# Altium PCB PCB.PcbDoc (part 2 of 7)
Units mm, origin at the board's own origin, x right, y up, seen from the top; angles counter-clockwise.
Board outline 243.2 x 142.8 mm, 4 copper layers (Top Layer, Layer 1, Layer 2, Bottom Layer), stack 0.603 mm thick; 451 components, 380 nets, 2276 pads, 1520 vias.
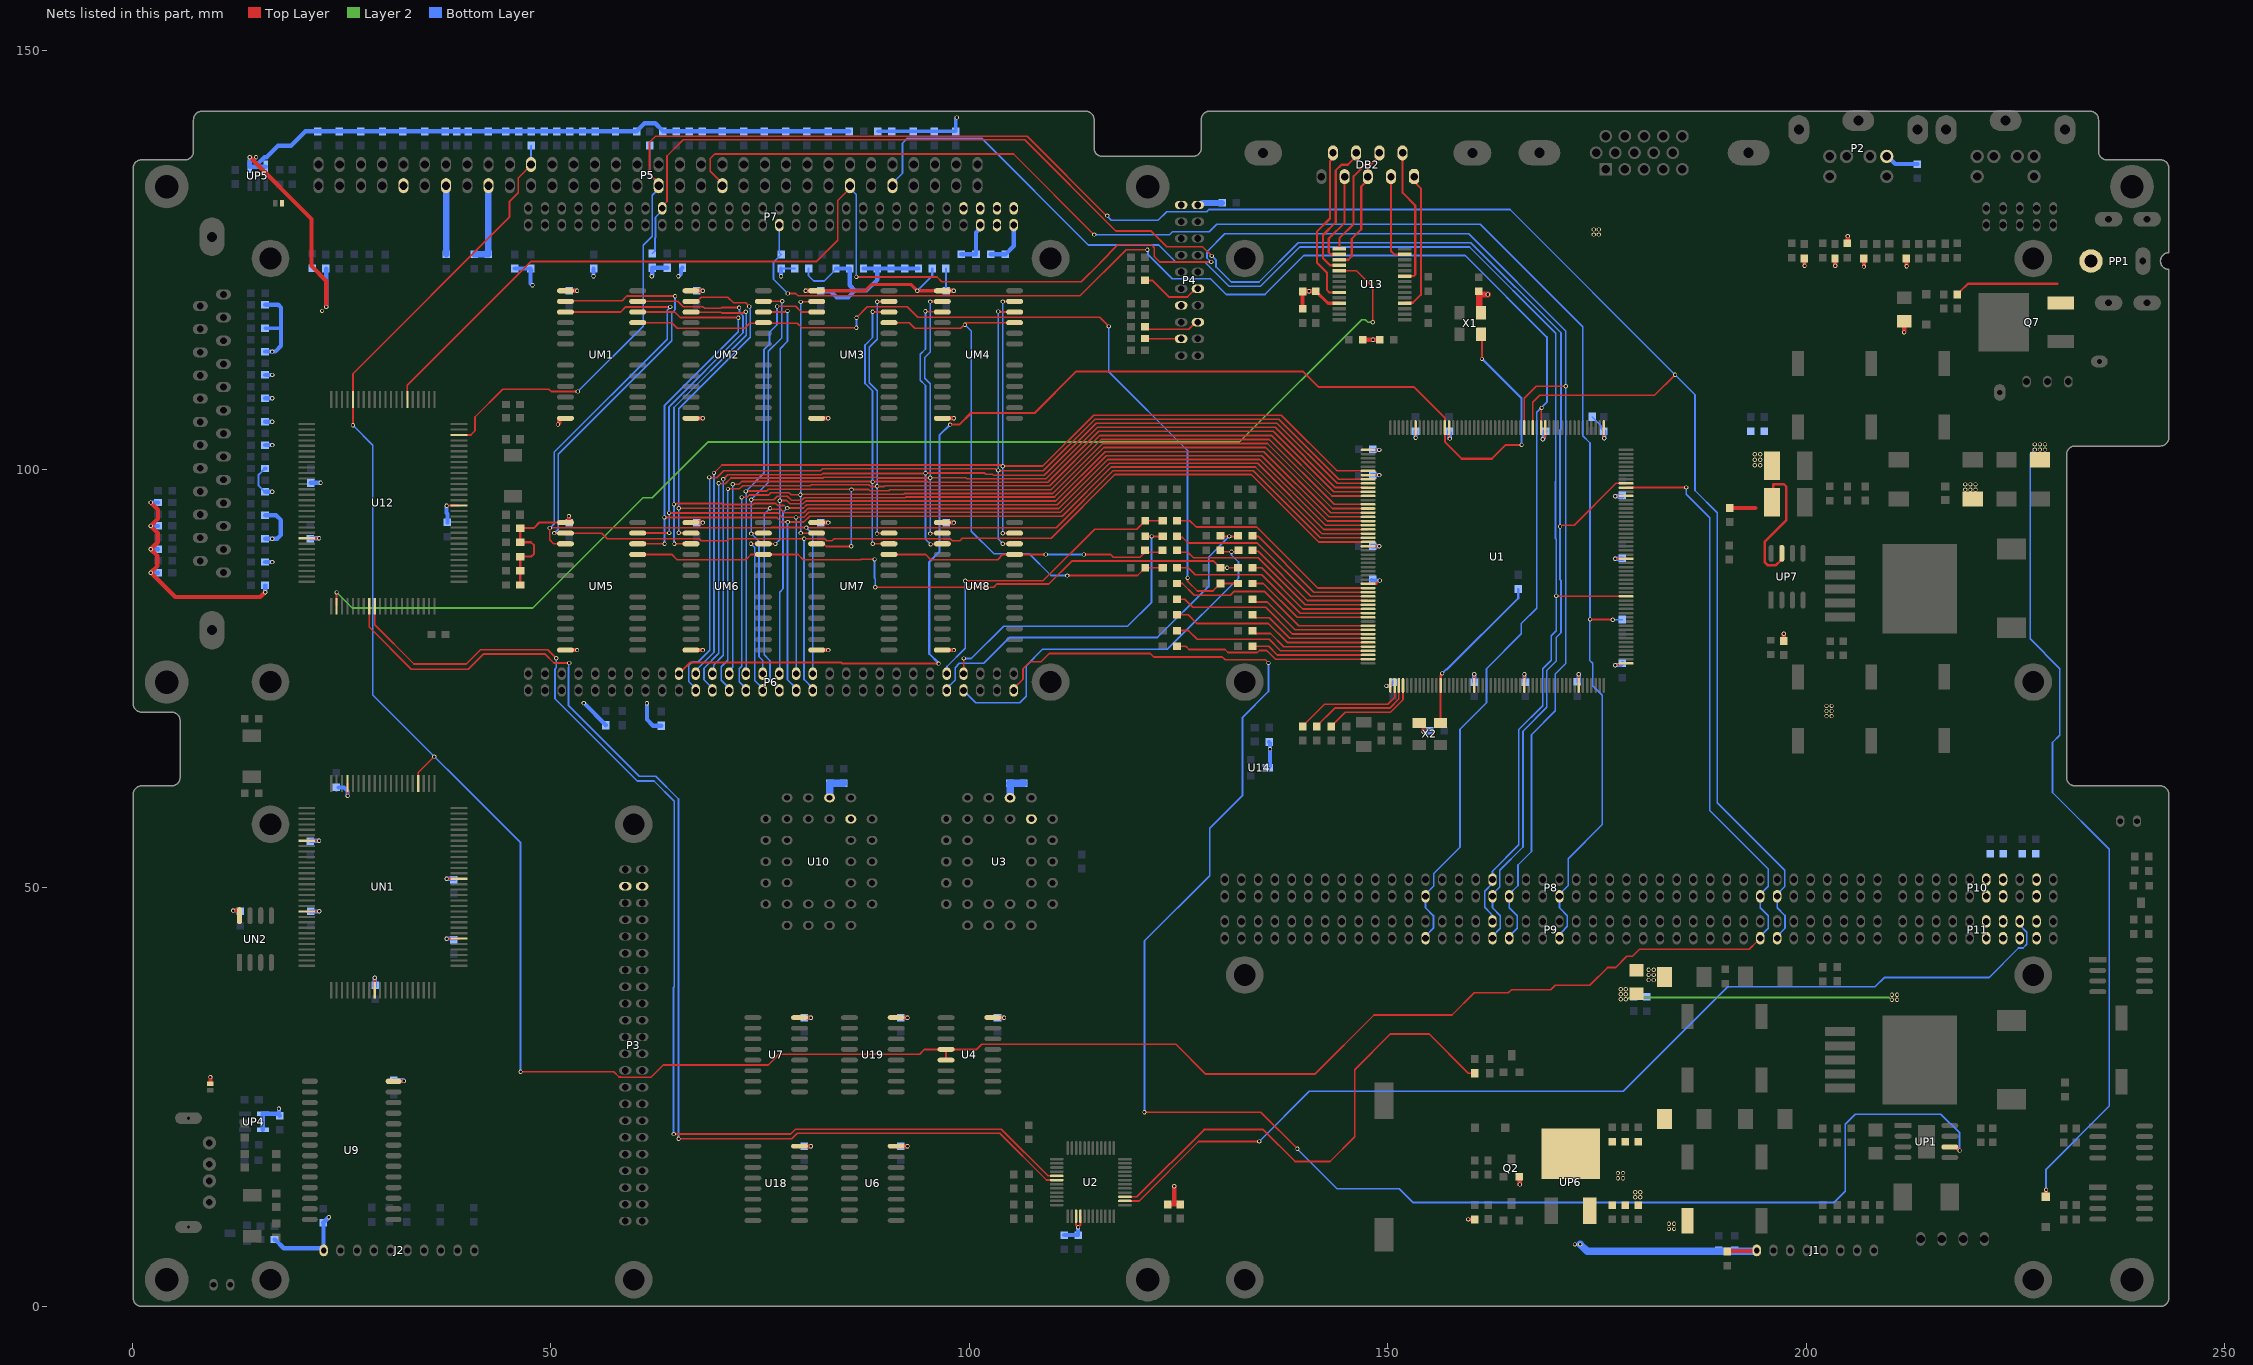
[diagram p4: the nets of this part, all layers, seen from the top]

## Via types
v1: diameter 0.508, hole 0.305, Top Layer to Bottom Layer, tented both sides, 1451 vias
v2: diameter 0.508, hole 0.3, Top Layer to Bottom Layer, 67 vias
v3: diameter 1.2, hole 1.2, Top Layer to Bottom Layer, 2 vias

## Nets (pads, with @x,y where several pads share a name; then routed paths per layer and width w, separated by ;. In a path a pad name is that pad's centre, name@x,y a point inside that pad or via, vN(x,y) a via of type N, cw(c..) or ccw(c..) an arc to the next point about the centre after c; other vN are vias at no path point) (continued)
12VSW#: R119.1 U2.27 | length 59.6
  Top Layer w0.203: U2.27@118.581,13.103 120.011,13.103 128.041,21.133 135.103,21.133 138.913,17.323 143.078,17.323 146.05,20.295 146.05,28.296 150.317,32.563 154.915,32.563 159.614,27.864 R119.1@160.376,27.864
14M: R93.1 U1.117 X2.3 | length 19.9
  Top Layer w0.254: X2.3@156.283,69.705 156.305,69.727 U1.117@156.305,74.206 156.313,74.215 156.313,75.401 156.475,75.563 v1(156.475,75.632)
  Bottom Layer w0.254: v1(156.475,75.632) 156.961,76.118 157.066,76.118 165.568,84.62 R93.1@165.568,85.717
+5V: C15.1 C16.1 C18.1 C19.1 C36.1 C37.1 C38.1 C39.1 C40.1 C41.1 C42.1 C43.1 C44.1 C45.1 C46.1 C47.1 C48.1 C49.1 C50.1 C51.1 C52.1 C53.1 C54.1 C55.1 C56.1 C57.1 C58.1 C59.1 C60.1 C61.1 C62.1 C63.1 C64.1 C65.1 C66.1 C67.1 C68.1 C69.1 C83.1 C84.1 C85.1 C119.1 C120.1 C121.1 C122.1 C123.1 C130.1 C131.1 C132.1 C133.1 C134.1 C135.1 C136.1 C137.1 C138.1 C139.1 C140.1 C141.1 C142.1 C143.1 C144.1 C145.1 C146.1 C147.1 C148.1 C149.1 J1.8 J2.10 JP1.1 JP2.1 P2.4 P3.41 P3.42 P4.19 P4.20 P7.55 P7.56 P7.57 P7.58 P10.7 P10.8 P10.9 P10.10 P11.7 P11.8 P11.9 P11.10 Q2.E R1.1 R3.2 R5.2 R21.1 R27.2 R28.2 R29.2 R30.2 R31.2 R32.2 R33.2 R34.2 R35.2 R36.2 R37.2 R38.2 R39.2 R40.2 R41.2 R42.2 R43.2 R44.2 R45.2 R46.2 R47.2 R48.2 R49.2 R50.2 R51.2 R52.2 R53.2 R54.2 R55.2 R56.2 R57.2 R58.2 R59.2 R60.2 R61.2 R62.2 R63.2 R64.2 R65.2 R66.2 R67.2 R68.2 R69.2 R70.2 R71.2 R72.2 R73.2 R74.2 R75.2 R76.2 R77.2 R78.2 R79.2 R80.2 R81.2 R82.2 R83.2 R84.2 R85.2 R86.2 R87.2 R92.1 R120.2 R121.2 R122.2 R123.2 R124.2 R125.2 R126.2 R127.2 R128.2 R129.2 R130.2 R131.2 R132.2 R133.2 R134.2 R135.2 R136.2 R137.2 R138.2 R139.2 R140.2 R141.2 R142.2 R143.2 R144.2 R152.2 RP1.1 RP2.1 RP4.2 U1.1 U1.15 U1.38 U1.46 U1.53 U1.59 U1.76 U1.85 U1.105 U1.125 U1.137 U1.150 U1.157 U1.182 U1.197 U2.15 U2.16 U3.31 U3.32 U4.16 U6.16 U7.16 U9.28 U10.31 U10.32 U12.15 U12.72 U13.11 U14.3 U18.16 U19.16 UM1.1 UM1.12 UM2.1 UM2.12 UM3.1 UM3.12 UM4.1 UM4.12 UM5.1 UM5.12 UM6.1 UM6.12 UM7.1 UM7.12 UM8.1 UM8.12 UN1.6 UN1.17 UN1.47 UN1.57 UN1.70 UN1.89 UN2.8 UP4.4 UP4.5 UP5.4 UP5.5 UP7.7 X1.4 X2.4 | length 471.1
  Top Layer w0.254: UN1.57@20.823,55.647 UN1.57@20.826,55.65 22.304,55.65 v1(22.309,55.656) ; U12.72@20.823,91.776 U12.72@20.826,91.779 22.304,91.779 v1(22.309,91.785) ; UN1.70@20.826,47.2 20.829,47.203 22.307,47.203 v1(22.312,47.209) ; UN1.47@25.698,62.478 UN1.47@25.701,62.475 25.701,60.997 v1(25.706,60.991) ; v1(28.945,39.259) 28.951,39.253 UN1.89@28.951,37.775 UN1.89@28.954,37.772 ; v1(37.542,43.944) 37.548,43.95 UN1.6@39.026,43.95 UN1.6@39.029,43.953 ; v1(37.542,51.094) 37.548,51.1 UN1.17@39.026,51.1 UN1.17@39.029,51.103 ; v1(37.542,95.673) 37.548,95.679 U12.15@39.026,95.679 U12.15@39.029,95.682 ; R143.2@46.341,86.198 R142.2@46.341,87.897 R141.2@46.341,89.597 47.657,89.597 47.992,89.932 47.992,90.926 47.614,91.303 46.348,91.303 R140.2@46.341,91.296 R139.2@46.341,92.995 47.957,92.995 48.621,93.659 UM5.1@51.739,93.659 ; U2.15@112.756,10.778 112.756,9.715 112.979,9.492 v1(112.979,9.449) 113.256,9.726 U2.16@113.256,10.778
  Top Layer w0.279: U1.85@147.647,86.336 147.651,86.34 148.598,86.34 148.989,86.731 v1(149.033,86.731) ; U1.76@147.647,90.836 147.649,90.834 v1(148.965,90.834) v1@148.967,90.831 ; U1.59@147.647,99.336 147.649,99.334 v1(148.965,99.334) v1@148.967,99.331 ; U1.53@147.647,102.336 147.649,102.334 v1(148.965,102.334) v1@148.967,102.331 ; v1(149.82,74.133) 150.295,74.133 150.305,74.142 U1.105@150.305,74.206 ; v1(153.302,103.801) 153.303,103.802 153.303,104.993 U1.46@153.305,104.994 ; U1.38@157.305,104.994 157.309,104.99 157.309,103.828 157.389,103.748 v1(157.389,103.686) ; U1.125@160.305,74.206 160.307,74.208 v1(160.307,75.524) v1@160.309,75.527 ; U1.137@166.305,74.206 166.307,74.208 v1(166.307,75.524) v1@166.309,75.527 ; v1(168.489,103.622) 168.489,103.684 168.801,103.995 168.801,104.99 U1.15@168.805,104.994 ; U1.150@172.805,74.206 172.807,74.208 v1(172.807,75.524) v1@172.809,75.527 ; U1.1@175.805,104.994 175.809,104.99 175.809,103.851 175.863,103.797 v1(175.863,103.735) ; v1@177.142,89.34 v1(177.144,89.338) 178.46,89.338 U1.182@178.463,89.336 ; v1(177.151,76.597) 177.195,76.64 177.512,76.64 177.707,76.836 U1.157@178.463,76.836 ; v1(177.177,96.796) 177.213,96.832 178.459,96.832 U1.197@178.463,96.836
  Top Layer w0.305: RP2.1@195.9,96.1 196.024,96.224 196.024,98.237 197.293,98.237 197.598,97.933 197.598,93.945 195.032,91.379 195.032,88.89 195.388,88.535 196.328,88.535 197.064,89.271 UP7.7@197.064,89.982
  Top Layer w0.381: UM3.1@81.756,121.35 87.538,121.35 88.302,122.113 93.001,122.113 v1(93.763,121.351) ; UM4.1@96.764,121.35 96.763,121.351 v1(93.763,121.351) ; C120.1@139.8,119.2 C120.1@139.808,119.208 ; C43.1@141.4,121.3 142.85,119.85 U13.11@144.2,119.85 ; v1(93.763,121.351) v1(93.763,121.351)
  Top Layer w0.508: v1(2.196,96.053) 3.059,95.189 3.059,94.123 v1(2.196,93.259) 3.034,92.421 3.034,91.303 v1(2.196,90.465) 2.983,89.678 2.983,88.458 v1(2.196,87.671) 5.117,84.75 15.277,84.75 v1(15.861,85.334) ; JP1.1@9.322,26.619 v2(9.322,27.407) ; v1(12.029,47.302) 12.743,47.302 12.79,47.255 UN2.8@12.79,46.688 ; v1(14.032,137.303) 21.398,129.937 21.398,124.298 23.151,122.545 v1(23.151,119.421) ; U9.28@31.2,26.9 31.224,26.924 32.42,26.924 v1(32.436,26.94) ; v1(50.837,105.375) 51.009,105.547 51.009,106.063 51.057,106.111 UM1.12@51.741,106.111 ; UM1.1@51.739,121.35 51.741,121.351 v1(53.123,121.351) ; UM5.1@51.74,93.66 52.111,93.66 52.157,93.706 v1(52.157,94.427) ; UM5.12@51.741,78.421 v1(53.123,78.421) ; UM6.1@66.747,93.658 UM6.1@66.747,93.659 UM6.1@66.747,93.659 v1(68.13,93.66) ; UM2.1@66.747,121.35 UM2.1@66.747,121.35 66.748,121.351 v1(68.13,121.351) ; UM6.12@66.749,78.421 v1(68.131,78.421) ; UM2.12@66.749,106.111 v1(68.131,106.111) ; U18.16@79.716,19.153 79.726,19.143 81.061,19.143 v1(81.063,19.142) ; U7.16@79.716,34.52 79.726,34.51 81.061,34.51 v1(81.063,34.509) ; v1(80.428,121.351) UM3.1@81.756,121.351 ; UM7.1@81.755,93.658 UM7.1@81.756,93.659 UM7.1@81.756,93.659 v1(83.138,93.66) ; UM7.12@81.756,78.419 v1(83.139,78.421) ; UM3.12@81.758,106.111 v1(83.139,106.111) ; U6.16@91.258,19.153 91.268,19.143 92.603,19.143 v1(92.604,19.142) ; U19.16@91.258,34.52 91.268,34.51 92.603,34.51 v1(92.604,34.509) ; UM8.1@96.763,93.658 UM8.1@96.764,93.659 96.765,93.66 v1(98.147,93.66) ; UM8.12@96.766,78.421 v1(98.147,78.421) ; UM4.12@96.766,106.111 v1(98.147,106.111) ; UM4.1@96.766,121.349 v1(98.145,121.349) ; U4.16@102.8,34.52 102.81,34.51 104.145,34.51 v1(104.146,34.509) ; R87.2@123.723,12.19 R86.2@125.197,12.19 ; 124.485,12.241 v2(124.485,14.376) ; C120.1@139.808,119.208 139.808,121.255 C119.1@139.816,121.263 139.854,121.301 v1(140.575,121.301) ; v1@140.537,121.281 141.381,121.281 C43.1@141.4,121.3 ; C123.1@147,115.5 147.196,115.5 148.204,115.5 v1(148.22,115.484) ; v1@148.236,115.5 C121.1@149,115.5 ; X2.4@153.743,69.705 153.919,69.705 154.265,69.359 v1(154.265,68.646) ; v1(159.599,10.404) 160.385,10.404 R5.2@160.387,10.406 ; Q2.E@165.708,15.51 165.746,15.472 v1(165.746,14.57) ; C42.1@190.562,6.569 190.625,6.632 193.999,6.632 J1.8@194.063,6.696 ; R152.2@190.83,95.401 193.876,95.401 ; v1(197.293,80.381) 197.293,79.543 R92.1@197.318,79.518 ; R43.2@199.757,125.214 199.782,125.189 v1(199.782,124.349) ; v1(203.44,124.349) R44.2@203.44,125.189 ; C18.1@204.938,127.041 v1(204.938,127.881) ; v1(206.869,124.245) R41.2@206.869,125.085 ; v1(211.669,116.373) 211.695,116.398 RP4.2@211.695,117.713 ; v1(211.974,124.271) R42.2@211.974,125.111
  Top Layer w0.762: C122.1@160.923,121.22 160.923,118.928 X1.4@161.142,118.709 ; C122.1@161.239,120.904 v1(161.925,120.904)
  Bottom Layer w0.203: R35.2@80.783,124 80.783,123.154 81.417,122.52 82.646,122.52 83.724,123.598 83.724,123.657 R53.2@84.067,124 ; R85.2@174.4,106.3 174.4,106.262 175.452,105.21 175.452,104.915 C60.1@175.8,104.567
  Bottom Layer w0.254: R132.2@15.859,97.323 15.821,97.323 15.079,98.065 15.079,99.375 15.821,100.117 R133.2@15.859,100.117 ; R21.1@77.5,124 R36.2@79.142,124 ; v1(93.763,121.351) 95.558,123.147 R59.2@95.558,124 ; R60.2@97.2,124 97.225,123.975 C142.1@97.225,121.35
  Bottom Layer w0.381: R127.2@15.859,116.881 17.74,116.881 17.766,116.906 ; R67.2@89.047,140.4 R66.2@90.74,140.4 R65.2@93.28,140.4 R64.2@95.82,140.4 R63.2@98.36,140.4 98.36,141.891 98.487,142.018 v1(98.487,142.052)
  Bottom Layer w0.508: v1(2.196,87.671) R121.2@3.061,87.671 ; v1(2.196,90.465) R122.2@3.061,90.465 ; v1(2.196,93.259) R123.2@3.061,93.259 ; v1(2.196,96.053) R124.2@3.061,96.053 ; v1(12.029,47.302) C37.1@12.779,47.302 ; UP5.4@14.032,136.167 UP5.5@15.932,136.167 ; UP5.4@14.032,136.167 v1(14.032,137.303) ; 14.959,136.49 15.772,137.303 16.039,137.303 17.41,138.674 18.96,138.674 20.685,140.4 R29.2@22.16,140.4 R52.2@24.734,140.4 R51.2@27.308,140.4 R50.2@29.882,140.4 R49.2@32.32,140.4 R48.2@34.911,140.4 R47.2@37.4,140.4 R27.2@38.772,140.4 R46.2@40.143,140.4 R45.2@42.531,140.4 R30.2@44.614,140.4 R31.2@46.141,140.4 R39.2@47.669,140.4 R32.2@49.196,140.4 R82.2@50.724,140.4 R37.2@52.252,140.4 R81.2@53.779,140.4 R80.2@55.307,140.4 R79.2@57.72,140.4 R78.2@60.26,140.4 60.26,140.438 61.189,141.367 62.46,141.367 63.389,140.438 R77.2@63.389,140.4 R76.2@64.954,140.4 R28.2@66.519,140.4 R75.2@68.083,140.4 R74.2@70.471,140.4 R73.2@73.062,140.4 R72.2@75.5,140.4 R71.2@78.04,140.4 R70.2@80.58,140.4 R69.2@83.12,140.4 R68.2@85.66,140.4 ; UP4.5@15.587,21.123 UP4.4@15.587,23.023 17.377,23.023 C15.1@17.512,22.888 ; R120.2@15.859,86.147 15.861,86.145 v1(15.861,85.334) ; R129.2@15.859,88.941 v1(16.724,88.941) ; R130.2@15.859,91.735 v1(16.724,91.735) 17.309,91.735 17.74,92.167 17.74,93.945 17.156,94.529 R131.2@15.859,94.529 ; R132.2@15.859,97.323 v1(16.724,97.323) ; R133.2@15.859,100.117 R133.2@15.86,100.116 ; R134.2@15.859,102.911 v1(16.724,102.911) ; R135.2@15.859,105.705 v1(16.724,105.705) ; R136.2@15.859,108.499 v1(16.724,108.499) ; R125.2@15.859,111.293 v1(16.724,111.293) ; R126.2@15.859,114.087 v1(16.724,114.087) 17.08,114.087 17.766,114.773 17.766,116.906 17.766,119.345 17.436,119.675 R128.2@15.859,119.675 ; R3.2@16.978,7.978 R3.2@17,8 17.038,8 18.088,6.95 22.627,6.95 J2.10@22.827,6.75 ; v1(17.512,23.638) C15.1@17.512,22.888 ; C15.1@17.6,22.8 C15.1@17.512,22.888 ; C85.1@21.297,55.647 22.301,55.647 v1(22.309,55.656) ; C19.1@21.297,91.776 22.301,91.776 v1(22.309,91.785) ; C48.1@21.3,47.2 22.304,47.2 v1(22.312,47.209) ; R144.2@21.3,98.4 v1(22.48,98.4) ; J2.10@22.854,6.696 22.854,6.723 J2.10@22.827,6.75 ; v1(23.151,119.421) R61.2@23.151,123.968 ; v1(23.481,10.658) 23.458,10.658 C83.1@22.8,10 22.827,9.973 J2.10@22.827,6.75 ; C84.1@24.638,62.001 25.288,62.001 25.698,61.592 25.698,61 v1(25.706,60.991) ; v1(28.945,39.259) 28.954,39.25 C69.1@28.954,38.246 ; C47.1@31.245,27.024 32.351,27.024 v1(32.436,26.94) ; v1(37.542,43.944) 37.551,43.953 C66.1@38.554,43.953 ; v1(37.542,51.094) 37.551,51.103 C49.1@38.554,51.103 ; v1(37.542,95.673) 37.542,94.799 37.643,94.698 C16.1@37.643,93.675 ; R138.2@45.676,124 R137.2@47.576,124 ; R137.2@47.692,123.802 47.608,123.802 47.578,123.771 47.578,122.223 v1(47.803,121.998) ; v1(52.157,94.427) 52.157,93.7 C149.1@52.199,93.658 ; C136.1@52.2,121.35 52.202,121.351 v1(53.123,121.351) ; v1(53.935,72.09) 56.552,69.474 R83.2@56.552,69.436 ; v1(55.089,123.079) R38.2@55.089,123.99 ; v1(61.479,72.075) 61.479,70.12 62.214,69.385 R84.2@63.181,69.385 ; v1(62.038,123.079) 62.106,123.146 R62.2@62.106,124.102 R33.2@63.913,124.102 ; v1(65.238,123.079) 65.53,123.371 65.53,123.911 R34.2@65.721,124.102 ; C135.1@67.284,121.349 C135.1@67.285,121.351 ; C135.1@67.437,121.35 v1@68.129,121.35 ; v1(68.13,93.66) C148.1@67.438,93.66 ; v1(77.489,123.079) R21.1@77.489,123.99 ; C40.1@80.275,19.142 v1(81.063,19.142) ; C45.1@80.275,34.509 v1(81.063,34.509) ; v1(80.428,121.351) 80.43,121.349 C144.1@82.217,121.35 ; C141.1@82.216,93.658 C141.1@82.217,93.659 82.217,93.66 v1(83.138,93.66) ; C144.1@82.217,121.35 82.295,121.271 83.429,121.271 84.111,120.589 85.558,120.589 86.346,121.377 ; R53.2@84.067,124 R54.2@85.708,124 85.708,122.014 86.346,121.377 ; R55.2@87.35,124 R56.2@88.992,124 ; C36.1@91.817,19.142 v1(92.604,19.142) ; C38.1@91.817,34.509 v1(92.604,34.509) ; R58.2@93.917,124 R40.2@92.275,124 R57.2@90.633,124 R56.2@88.992,124 ; C140.1@97.224,93.658 C140.1@97.225,93.659 C140.1@97.225,93.659 v1(98.147,93.66) ; C142.1@97.421,121.351 98.144,121.351 v1(98.145,121.349) ; C139.1@99.035,125.7 C138.1@100.79,125.7 100.79,128.307 101.3,128.817 P7.55@101.3,129.2 ; C39.1@103.359,34.509 v1(104.146,34.509) ; C143.1@104.8,62.559 C143.1@104.831,62.527 ; C143.1@104.831,62.559 C143.1@104.831,62.527 ; U3.32@104.862,60.772 104.831,60.804 C143.1@104.831,62.525 C143.1@104.831,62.527 ; C51.1@111.328,8.533 C50.1@112.979,8.533 112.981,8.534 112.981,9.447 v1(112.979,9.449) ; U14.3@135.636,64.364 135.712,64.364 135.915,64.567 v1(135.915,66.599) 135.915,67.333 R1.1@135.799,67.449 ; C54.1@148.057,86.807 148.133,86.731 v1(149.033,86.731) ; C65.1@148.074,90.831 148.076,90.834 v1(148.965,90.834) ; C64.1@148.074,99.331 148.076,99.334 v1(148.965,99.334) ; C63.1@148.074,102.331 148.076,102.334 v1(148.965,102.334) ; v1(149.82,74.133) 150.191,74.133 C67.1@150.659,74.6 ; C41.1@153.3,104.567 153.302,104.564 v1(153.302,103.801) ; v1@154.264,68.65 154.998,68.65 C62.1@155.026,68.623 ; C44.1@157.3,104.567 157.3,104.46 157.389,104.371 v1(157.389,103.686) ; v1(160.307,75.524) 160.307,74.635 C68.1@160.309,74.633 ; v1(166.307,75.524) 166.307,74.635 C57.1@166.309,74.633 ; v1(168.489,103.622) 168.635,103.767 168.635,104.397 C59.1@168.802,104.564 ; v1(172.807,75.524) 172.807,74.635 C56.1@172.809,74.633 ; v1(175.863,103.735) C60.1@175.863,104.503 ; v1(177.144,89.338) 178.033,89.338 C58.1@178.036,89.34 ; v1(177.151,76.597) 177.197,76.642 177.838,76.642 C55.1@178.033,76.838 ; v1(177.177,96.796) 177.991,96.796 C61.1@178.036,96.84 ; P2.4@209.6,137.2 209.895,137.2 210.607,136.488 C131.1@213.27,136.488 ; C148.1@67.437,93.659 C148.1@67.438,93.66 ; 86.346,121.377 87.717,121.377 88.992,122.651 R56.2@88.992,124
  Bottom Layer w0.762: P4.19@127.3,131.6 127.614,131.6 127.856,131.842 C130.1@130.186,131.842
  Bottom Layer w0.889: U10.32@83.298,60.772 83.299,60.774 83.299,62.525 C145.1@85,62.525 ; C143.1@104.831,62.525 C137.1@106.488,62.525 ; U3.32@104.862,60.747 104.863,60.748 C143.1@104.863,62.5 ; v1(172.985,7.407) 173.798,6.594 194.011,6.594 194.063,6.645 J1.8@194.063,6.696
  other v1: 172.34,7.407 193.832,100.498 194.499,100.498 193.832,101.165 194.499,101.165 193.832,101.831 194.499,101.831 22.668,118.938 14.772,137.303
+12R: DP3.K DP10.K R109.1
  other v1: 181.139,39.005 181.748,39.005 181.139,39.614 181.748,39.614 181.139,40.224 181.748,40.224 202.404,70.535 203.013,70.535 202.404,71.145 203.013,71.145 202.404,71.755 203.013,71.755 218.985,97.602 219.594,97.602 220.204,97.602 218.985,98.212 219.594,98.212 220.204,98.212
+12V: C20.1 C21.1 C31.1 C32.1 C71.1 C72.1 C73.1 C74.1 P5.17 P7.59 P7.60 P10.3 P11.3 R109.2 | length 47.7
  Layer 2 w0.203: v1(178.421,36.693) 178.479,36.752 178.665,36.752 178.819,36.906 209.873,36.906 210.141,36.638 v1(210.224,36.638) ; v1@210.224,36.642 v1@210.421,36.642
  Bottom Layer w0.508: C21.1@102.545,125.7 C20.1@104.3,125.7 105.3,126.7 P7.59@105.3,129.2
  Bottom Layer w0.762: C72.1@40.869,125.7 C32.1@42.5,125.7 42.525,125.725 42.525,133.875 P5.17@42.55,133.9
  other v1: 210.833,36.638 177.811,36.693 210.224,37.247 210.833,37.247 177.811,37.303 178.421,37.303 177.811,37.912 178.421,37.912 174.585,128.057 175.195,128.057 174.585,128.667 175.195,128.667
-5V: C29.1 C75.1 C76.1 P5.9 P7.54 P11.6 UP6.3
  other v1: 179.538,13.046 180.148,13.046 179.538,13.655 180.148,13.655
-12V: C27.1 C70.1 C81.1 C82.1 CP12.2 DP9.A P5.13 P10.4 P11.4 UP6.2 | length 8.2
  Bottom Layer w0.762: P5.13@37.47,133.9 37.485,133.885 37.485,125.715 C81.1@37.5,125.7 C81.1@37.495,125.695
  other v1: 183.577,9.261 184.187,9.261 183.577,9.871 184.187,9.871 177.481,15.332 178.091,15.332 177.481,15.941 178.091,15.941
ACIN: DP1.A DP5.A PP1.1 Q7.2 R105.1 | length 109.8
  Top Layer w0.254: R105.1@218.045,120.92 218.045,120.958 218.362,121.275 218.4,121.275 219.315,122.19 229.978,122.19
  Top Layer w0.508: DP1.A@228.6,13.1 228.637,13.137 v1(228.637,13.935)
  Bottom Layer w0.203: v1(227.29,102.378) 226.732,101.819 226.732,79.756 230.276,76.211 230.276,68.254 229.399,67.376 229.399,61.407 236.18,54.626 236.18,23.942 228.637,16.399 v1(228.637,13.935)
  other v1: 227.9,102.378 228.51,102.378 227.29,102.987 227.9,102.987 228.51,102.987
AEN: P5.22 P8.16 P9.16 R39.1 U1.199 U4.4 U4.5 U12.46 UN1.34 | length 357.6
  Top Layer w0.203: U12.46@26.351,108.354 26.351,111.445 45.045,130.14 45.045,131.99 46.112,133.056 46.112,134.813 47.63,136.331 P5.22@47.63,136.44 ; v1(26.351,105.273) U12.46@26.351,108.354 ; UN1.34@34.151,62.475 34.151,63.797 v1(36.054,65.7) ; v1(46.38,28.042) 57.506,28.042 58.141,27.407 58.305,27.407 58.317,27.395 61.965,27.395 63.425,28.856 75.973,28.856 77.241,30.124 94.056,30.124 94.642,30.71 U4.4@97.212,30.71 ; U4.5@97.212,29.44 U4.4@97.212,30.71 ; U1.199@178.463,97.836 178.473,97.846 185.624,97.846 v1(185.634,97.856) ; P9.16@194.5,44 194.5,43.966 194.132,43.598 194.098,43.598 193.172,42.672 180.061,42.672 179.222,41.834 178.537,41.834 177.19,40.488 176.245,40.488 174.137,38.379 169.977,38.379 169.443,37.846 164.77,37.846 164.389,37.465 160.299,37.465 157.658,34.823 148.336,34.823 141.275,27.762 128.245,27.762 124.689,31.318 101.473,31.318 100.865,30.71 U4.4@97.212,30.71
  Bottom Layer w0.203: v1(26.351,105.273) 28.713,102.911 28.713,73.049 46.379,55.383 v1@46.379,28.016 ; P5.22@47.63,136.44 47.63,138.661 R39.1@47.669,138.7 ; v1(185.634,97.856) 185.634,97.054 188.454,94.235 188.454,59.247 195.438,52.263 195.438,50.188 194.5,49.25 P8.16@194.5,49 194.5,47.638 195.437,46.701 195.437,45.187 194.5,44.25 P9.16@194.5,44
ALE: P5.55 P8.47 P9.47 U1.173 | length 179.4
  Top Layer w0.203: v1(170.115,84.895) 170.166,84.844 178.455,84.844 U1.173@178.463,84.836
  Bottom Layer w0.203: P5.55@90.81,133.9 90.81,134.2 92.01,135.4 92.01,138.979 92.594,139.563 101.462,139.563 114.202,126.822 122.607,126.822 124.634,124.795 128.114,124.795 131.011,121.898 134.772,121.898 139.458,126.584 159.751,126.584 170.051,116.284 170.051,98.565 170.013,98.527 170.013,91.781 170.115,91.68 v1(170.115,84.895) 170.115,80.729 169.513,80.127 169.513,77.225 168.484,76.196 168.484,71.784 165.64,68.939 165.64,55.154 162.5,52.014 P8.47@162.5,51 ; P9.47@162.384,46.116 162.384,46.865 161.558,47.691 161.558,49.622 P8.47@162.5,50.564
AMA0: RM1.1 U1.108 | length 11.7
  Top Layer w0.203: RM1.1@143.213,69.305 143.213,69.343 143.556,69.686 143.594,69.686 144.891,70.983 150.303,70.983 151.805,72.485 U1.108@151.805,74.206
AMA1: RM2.1 U1.107 | length 12.8
  Top Layer w0.203: RM2.1@141.513,69.305 141.513,69.343 143.661,71.491 150.227,71.491 151.305,72.569 U1.107@151.305,74.206
AMA2: RM3.1 U1.106 | length 13.9
  Top Layer w0.203: RM3.1@139.813,69.305 139.813,69.343 142.418,71.948 149.973,71.948 150.805,72.78 U1.106@150.805,74.206
AMA3: RM4.1 U1.103 | length 23.7
  Top Layer w0.203: RM4.1@124.8,78.875 125.85,78.875 126.239,78.486 130.531,78.486 130.891,78.126 134.409,78.126 134.652,78.369 135.537,78.369 136.57,77.336 U1.103@147.647,77.336
AMA4: RM5.1 U1.102 | length 14.3
  Top Layer w0.203: RM5.1@133.8,78.875 135.756,78.875 136.796,77.836 U1.102@147.647,77.836
AMA5: RM6.1 U1.101 | length 23.8
  Top Layer w0.203: RM6.1@124.8,80.75 126.175,80.75 127.225,79.7 135.806,79.7 137.17,78.336 U1.101@147.647,78.336
AMA6: RM7.1 U1.100 | length 14.6
  Top Layer w0.203: RM7.1@133.8,80.75 134.143,80.407 135.977,80.407 137.548,78.836 U1.100@147.647,78.836
AMA7: RM8.1 U1.99 | length 24.2
  Top Layer w0.203: RM8.1@124.8,82.625 126.15,82.625 127.175,81.6 135.698,81.6 137.963,79.336 U1.99@147.647,79.336
AMA8: RM9.1 U1.98 | length 15
  Top Layer w0.203: RM9.1@133.8,82.625 134.143,82.282 135.835,82.282 138.282,79.836 U1.98@147.647,79.836
AMA9: RM10.1 U1.97 | length 24.6
  Top Layer w0.203: RM10.1@124.8,84.5 125.736,84.5 126.705,83.531 135.393,83.531 138.588,80.336 U1.97@147.647,80.336
AMA10: RM11.1 U1.96 | length 15.4
  Top Layer w0.203: RM11.1@133.8,84.5 134.143,84.157 135.58,84.157 138.901,80.836 U1.96@147.647,80.836
AMA11: RM12.1 U1.95 | length 25.3
  Top Layer w0.203: RM12.1@124.8,86.375 124.807,86.368 125.468,86.368 126.848,84.988 131.166,84.988 131.588,85.41 135.292,85.41 139.366,81.336 U1.95@147.647,81.336
ATCLK: P5.39 P8.40 P9.40 R94.2 | length 198.7
  Top Layer w0.203: P5.39@70.49,133.9 70.49,134.2 69.048,135.642 69.048,137.15 69.582,137.684 105.269,137.684 114.895,128.057 v1(114.921,128.057) ; v1(174.154,82.083) 174.166,82.07 176.859,82.07 v1(176.871,82.058)
  Bottom Layer w0.203: v1(114.921,128.057) 123.912,128.057 124.26,128.405 128.654,128.405 129.551,129.302 139.283,129.302 161.047,129.302 173.29,117.059 173.29,104.029 174.154,103.165 174.154,82.134 v1@174.179,82.108 ; P9.40@170.5,44 170.5,44.466 170.756,44.722 170.756,44.726 171.437,45.407 171.437,46.701 170.5,47.638 P8.40@170.5,49 170.5,49.25 171.549,50.299 171.549,53.508 175.627,57.586 175.627,73.01 174.458,74.178 174.458,76.855 174.128,77.185 174.128,82.058 v1(174.154,82.083) ; v1(176.871,82.058) 177.987,82.058 R94.2@177.989,82.056
BD0: P6.35 U1.75 UM1.2 UM5.2 | length 170.9
  Top Layer w0.203: v1(50.405,92.395) 50.408,92.392 51.736,92.392 UM5.2@51.739,92.389 56.075,92.389 56.736,91.729 67.711,91.729 67.969,91.471 71.065,91.471 71.323,91.729 v1(80.25,91.729) 82.719,91.729 82.977,91.471 83.593,91.471 83.85,91.729 97.728,91.729 97.966,91.49 98.877,91.49 99.167,91.78 109.763,91.78 117.377,99.394 133.664,99.394 141.722,91.336 U1.75@147.647,91.336 ; UM1.2@51.739,120.08 51.817,120.157 58.507,120.157 59.066,120.716 64.807,120.716 v1(64.832,120.691)
  Bottom Layer w0.203: v1(50.405,92.395) 50.876,92.867 50.876,101.808 64.426,115.357 64.426,118.684 64.833,119.092 v1(64.832,120.691) v1(64.832,120.691) ; v1@80.25,91.735 v1(80.25,91.729) 80.25,74.9 81.3,73.85 P6.35@81.3,73.6
BD1: P6.36 U1.74 UM1.3 UM5.3 | length 170.4
  Top Layer w0.203: UM5.3@51.739,91.119 50.314,91.119 49.846,91.588 49.846,92.98 49.916,93.05 76.347,93.05 76.353,93.056 v1(80.529,93.056) 80.535,93.05 110.372,93.05 117.164,99.841 133.924,99.841 141.929,91.836 U1.74@147.647,91.836 ; UM1.3@51.739,118.81 58.328,118.81 58.939,119.421 v1(64.275,119.42) v1(64.275,119.42)
  Bottom Layer w0.203: v1(49.871,93.005) 49.922,93.005 50.419,93.502 50.419,102.087 63.892,115.56 63.892,119.012 64.275,119.394 v1(64.275,119.42) ; v1(80.529,93.056) 81.3,92.285 P6.36@81.3,75.6
BD2: P6.33 U1.73 UM1.22 UM5.22 | length 157.1
  Top Layer w0.203: UM5.22@60.375,91.119 60.378,91.122 63.584,91.122 v1(63.587,91.125) ; UM1.22@60.375,118.81 64.808,118.81 65.467,118.151 72.376,118.151 v1(72.401,118.126) ; v1(63.562,94.275) 63.587,94.25 65.764,94.25 65.784,94.269 77.005,94.269 77.557,93.716 v1(78.291,93.716) 80.228,93.716 80.939,94.427 111.078,94.427 116.939,100.289 134.183,100.289 142.136,92.336 U1.73@147.647,92.336
  Bottom Layer w0.203: v1(63.587,91.125) 63.575,91.138 63.575,94.262 v1(63.562,94.275) 63.562,107.624 72.401,116.463 v1(72.401,118.126) ; v1(78.291,93.716) 78.269,93.694 78.269,74.881 79.3,73.85 P6.33@79.3,73.6
BD3: P6.34 U1.72 UM1.23 UM5.23 | length 155.4
  Top Layer w0.203: UM5.23@60.375,92.389 60.391,92.405 64.13,92.405 v1(64.146,92.421) ; UM1.23@60.375,120.08 65.174,120.08 65.811,119.443 68.163,119.443 68.363,119.243 70.328,119.243 70.43,119.345 v1(72.477,119.345) ; v1(64.121,94.808) 77.126,94.808 77.659,94.275 v1(79.285,94.275) 79.31,94.3 80.237,94.3 80.814,94.877 110.877,94.877 116.736,100.736 134.443,100.736 142.343,92.836 U1.72@147.647,92.836
  Bottom Layer w0.203: v1(64.146,92.421) 64.133,92.434 64.133,94.796 v1(64.121,94.808) 64.121,107.497 72.96,116.336 72.96,118.357 72.531,118.786 72.531,119.291 v1(72.477,119.345) ; v1(79.285,94.275) 79.3,94.26 P6.34@79.3,75.6
BD4: P6.31 U1.71 UM2.2 UM6.2 | length 151.2
  Top Layer w0.203: v1(65.264,92.446) 65.292,92.418 66.719,92.418 UM6.2@66.747,92.389 ; v1(65.264,95.367) 76.081,95.367 v1@76.186,95.262 ; UM2.2@66.747,120.08 67.459,120.08 67.956,120.577 71.14,120.577 71.814,119.904 73.265,119.904 v1(73.697,119.472) ; v1(76.186,95.367) v1@76.186,95.262 ; U1.71@147.647,93.336 142.55,93.336 134.702,101.184 116.547,101.184 110.69,95.328 80.69,95.328 80.196,94.834 77.873,94.834 77.445,95.262 v1@76.186,95.262
  Bottom Layer w0.203: v1(65.264,92.446) 65.264,107.243 73.828,115.808 73.828,119.258 73.697,119.389 v1(73.697,119.472) ; v1(76.186,95.367) 75.475,94.656 75.475,77.867 76.186,77.155 76.186,74.964 77.3,73.85 P6.31@77.3,73.6
BD5: P6.32 U1.70 UM2.3 UM6.3 | length 149.3
  Top Layer w0.203: v1(64.705,95.821) 64.763,95.88 64.986,95.88 65.032,95.926 70.389,95.926 70.493,95.821 74.157,95.821 74.261,95.926 76.869,95.926 77.097,95.697 77.856,95.697 78.161,95.393 v1(78.243,95.393) 80.18,95.393 80.565,95.778 110.504,95.778 116.372,101.645 134.948,101.645 142.758,93.836 U1.70@147.647,93.836 ; v1(64.756,91.125) 64.759,91.122 66.744,91.122 UM6.3@66.747,91.119 ; UM2.3@66.747,118.81 66.759,118.798 70.283,118.798 70.397,118.684 73.034,118.684 73.187,118.838 v1(73.27,118.838)
  Bottom Layer w0.203: v1(64.756,91.125) 64.705,91.176 v1(64.705,95.821) 64.705,107.396 73.341,116.032 73.341,118.515 73.328,118.528 73.328,118.779 v1(73.27,118.838) ; P6.32@77.3,75.6 77.326,75.626 77.326,85.347 77.732,85.753 77.732,94.881 v1(78.243,95.393)
BD6: P6.29 U1.69 UM2.22 UM6.22 | length 128.7
  Top Layer w0.203: v1(73.9,91.125) 73.903,91.122 75.298,91.122 75.301,91.125 75.317,91.11 76.811,91.11 v1(76.821,91.1) ; UM2.22@75.383,118.81 75.384,118.811 78.058,118.811 78.186,118.938 v1(78.269,118.938) ; v1@77.329,96.293 78.167,96.293 78.559,95.901 80.113,95.901 80.44,96.228 110.317,96.228 116.22,102.13 135.17,102.13 142.965,94.336 U1.69@147.647,94.336
  Bottom Layer w0.203: v1(73.9,91.125) 74.357,90.668 74.357,74.793 75.3,73.85 P6.29@75.3,73.6 ; v1(76.821,91.1) 77.326,91.605 77.326,96.253 77.387,96.315 77.387,96.51 77.405,96.528 77.405,114.443 78.269,115.306 v1(78.269,118.938)
  other v1: 77.329,96.256
BD7: P6.30 U1.68 UM2.23 UM6.23 | length 130.3
  Top Layer w0.203: v1(73.925,96.38) 76.612,96.38 77.047,96.815 78.243,96.815 78.751,96.307 79.945,96.307 80.275,96.637 92.336,96.637 92.42,96.721 110.175,96.721 116.068,102.615 135.393,102.615 143.172,94.836 U1.68@147.647,94.836 ; v1(73.951,92.345) 73.973,92.367 75.361,92.367 UM6.23@75.383,92.389 ; UM2.23@75.383,120.08 75.397,120.093 77.62,120.093 v1(77.634,120.107)
  Bottom Layer w0.203: v1(73.925,96.38) v1@73.951,96.405 ; v1@73.938,96.367 73.938,92.357 v1(73.951,92.345) 74.865,91.43 74.865,77.616 75.3,77.181 P6.30@75.3,75.6 ; v1@73.951,96.38 v1@73.951,96.405 ; v1(77.634,120.107) 77.583,120.056 77.583,115.713 75.983,114.112 75.983,98.437 v1@73.951,96.405
BD8: P6.27 U1.67 UM3.2 UM7.2 | length 136
  Top Layer w0.203: v1(72.782,96.663) 73.417,96.663 73.697,96.942 76.008,96.942 76.287,97.221 78.446,97.221 78.698,96.97 v1(79.818,96.97) 79.876,97.029 80.092,97.029 80.107,97.044 92.168,97.044 92.252,97.128 109.945,97.128 115.917,103.1 135.615,103.1 143.379,95.336 U1.67@147.647,95.336 ; v1(79.859,92.395) 79.862,92.392 81.753,92.392 UM7.2@81.756,92.389 ; v1(79.859,120.015) 79.891,120.047 81.724,120.047 UM3.2@81.756,120.08
  Bottom Layer w0.203: v1(72.782,96.663) 72.808,96.637 72.808,76.496 72.495,76.183 72.495,74.655 73.3,73.85 P6.27@73.3,73.6 ; v1(79.818,96.97) 79.859,96.929 v1(79.859,92.395) ; v1@79.859,96.97 v1(79.859,120.015)
BD9: P6.28 U1.66 UM3.3 UM7.3 | length 141.8
  Top Layer w0.203: v1(73.29,97.374) 73.341,97.425 75.779,97.425 75.983,97.628 85.914,97.628 85.939,97.602 87.988,97.602 88.14,97.45 90.363,97.45 90.491,97.578 109.758,97.578 115.765,103.585 135.837,103.585 143.586,95.836 U1.66@147.647,95.836 ; v1(77.024,119.472) 77.049,119.497 79.234,119.497 79.921,118.81 UM3.3@81.756,118.81 ; UM7.3@81.756,91.119 82.577,91.119 82.901,90.795 85.863,90.795 v1(85.889,90.821)
  Bottom Layer w0.203: P6.28@73.3,75.6 73.341,75.641 73.341,97.323 v1(73.29,97.374) 75.449,99.533 75.449,114.316 76.11,114.976 76.11,116.398 77.024,117.313 v1(77.024,119.472) ; v1(85.889,90.821) 85.901,90.833 85.901,97.59 v1(85.914,97.602)
BD10: P6.25 U1.64 UM3.23 UM7.23 | length 138.5
  Top Layer w0.203: v1(71.157,97.679) 72.528,97.679 72.921,98.072 81.018,98.072 81.107,98.161 87.994,98.161 88.197,97.958 89.826,97.958 89.918,98.05 109.594,98.05 115.613,104.069 136.08,104.069 143.314,96.836 U1.64@147.647,96.836 ; v1(88.962,92.345) 88.984,92.367 90.369,92.367 UM7.23@90.392,92.389 ; v1(88.987,120.031) 89.012,120.055 90.367,120.055 UM3.23@90.392,120.08
  Bottom Layer w0.203: v1(71.157,97.679) 71.14,97.662 71.14,77.215 70.344,76.419 70.344,74.806 71.3,73.85 P6.25@71.3,73.6 ; v1(88.962,92.345) 88.975,92.357 v1(88.975,98.009) 88.987,98.022 88.987,109.411 88.048,110.35 88.048,114.62 88.995,115.568 88.995,119.244 88.987,119.251 v1(88.987,120.031)
BD11: P6.26 U1.63 UM3.22 UM7.22 | length 136.8
  Top Layer w0.203: v1(71.715,98.237) 72.477,98.237 72.808,98.568 94.97,98.568 95.081,98.457 109.364,98.457 115.461,104.554 136.302,104.554 143.521,97.336 U1.63@147.647,97.336 ; v1(88.436,118.837) 88.45,118.823 90.378,118.823 UM3.22@90.392,118.81 ; v1(88.454,91.125) 88.457,91.122 90.389,91.122 UM7.22@90.392,91.119
  Bottom Layer w0.203: P6.26@71.3,75.6 71.3,75.952 71.715,76.367 v1(71.715,98.237) ; v1(88.436,118.837) 88.429,118.829 88.429,115.763 87.54,114.874 87.54,110.277 88.429,109.388 v1(88.429,98.517) 88.403,98.491 88.403,91.176 v1(88.454,91.125)
BD12: P6.23 U1.62 UM4.2 UM8.2 | length 140.7
  Top Layer w0.203: v1(70.039,98.339) 70.09,98.288 70.829,98.288 71.515,98.974 82.501,98.974 82.602,99.076 88.836,99.076 88.938,98.974 95.27,98.974 v1(95.312,99.016) 99.577,99.016 99.708,98.885 109.156,98.885 115.31,105.039 136.525,105.039 143.728,97.836 U1.62@147.647,97.836 ; v1(95.312,92.345) 95.334,92.367 96.742,92.367 UM8.2@96.764,92.389 ; v1(95.312,120.056) 95.324,120.068 96.752,120.068 UM4.2@96.764,120.08
  Bottom Layer w0.203: P6.23@69.3,73.6 69.3,73.85 68.286,74.864 68.286,76.266 70.064,78.044 70.064,98.314 v1(70.039,98.339) ; v1(95.312,92.345) v1(95.312,99.016) 95.312,110.252 94.652,110.912 94.652,113.376 95.312,114.036 v1(95.312,120.056)
BD13: P6.24 U1.61 UM4.3 UM8.3 | length 138.9
  Top Layer w0.203: v1(70.598,98.847) 71.131,99.38 82.332,99.38 82.468,99.516 94.736,99.516 v1(94.753,99.533) ; v1(94.742,118.897) 94.786,118.854 96.72,118.854 UM4.3@96.764,118.81 ; v1@94.753,99.574 101.82,99.574 101.951,99.444 102.76,99.444 102.913,99.292 108.926,99.292 115.158,105.524 136.747,105.524 143.935,98.336 U1.61@147.647,98.336 ; v1(95.363,91.049) 95.398,91.084 96.729,91.084 UM8.3@96.764,91.119
  Bottom Layer w0.203: P6.24@69.3,75.6 69.452,75.752 69.452,76.645 70.598,77.79 v1@70.598,98.872 ; v1(94.742,118.897) 94.753,118.886 94.753,114.392 94.118,113.757 94.118,110.658 94.753,110.023 v1(94.753,99.533) 94.753,91.659 v1(95.363,91.049)
BD14: P6.21 U1.60 UM4.22 UM8.22 | length 143.5
  Top Layer w0.203: v1(68.921,99.05) 68.972,98.999 69.81,98.999 70.639,99.828 82.206,99.828 82.469,100.092 103.083,100.092 103.171,100.003 103.242,100.003 103.358,99.888 v1(103.44,99.888) ; v1@103.407,99.947 103.524,99.83 103.766,99.83 108.827,99.829 115.006,106.009 136.969,106.009 144.142,98.836 U1.60@147.647,98.836 ; v1(103.44,118.872) 103.498,118.814 103.723,118.814 103.727,118.81 UM4.22@105.4,118.81 ; v1(103.999,91.125) 104.002,91.122 105.397,91.122 UM8.22@105.4,91.119
  Bottom Layer w0.203: P6.21@67.3,73.6 67.3,73.85 66.486,74.664 66.486,76.574 66.94,77.028 67.601,77.028 68.972,78.4 68.972,98.999 v1(68.921,99.05) ; v1(103.44,99.888) 103.44,91.684 v1(103.999,91.125) ; v1@103.44,99.914 v1(103.44,118.872)
BD15: P6.22 U1.58 UM4.23 UM8.23 | length 139.3
  Top Layer w0.203: v1(69.48,99.584) 70.436,100.54 103.765,100.54 103.916,100.388 v1(103.999,100.388) ; v1(103.999,92.37) 104.008,92.38 105.39,92.38 UM8.23@105.4,92.389 ; v1@103.999,100.409 108.771,100.409 114.855,106.493 137.263,106.493 143.92,99.836 U1.58@147.647,99.836 ; v1(103.999,120.056) 104.011,120.068 105.388,120.068 UM4.23@105.4,120.08
  Bottom Layer w0.203: P6.22@67.3,75.6 67.3,75.982 69.48,78.162 v1(69.48,99.584) ; v1(103.999,92.37) v1@103.999,100.409 ; v1(103.999,100.388) v1(103.999,120.056)
BHE#: P7.18 P8.48 P9.48 R62.1 U1.200 | length 220.5
  Top Layer w0.203: P7.18@63.3,131.2 63.3,131.455 63.867,132.021 63.867,137.447 65.808,139.388 106.612,139.388 117.52,128.48 121.711,128.48 123.582,126.609 127.856,126.609 128.942,125.523 v1(128.942,125.517) ; v1(170.572,93.183) 170.655,93.183 170.807,93.335 172.257,93.335 177.258,98.336 U1.200@178.463,98.336
  Bottom Layer w0.203: R62.1@62.106,125.802 62.449,126.145 62.449,127.675 62.495,127.721 62.495,130.145 63.3,130.95 P7.18@63.3,131.2 ; v1(128.942,125.517) 128.973,125.517 129.475,125.015 129.475,124.196 131.278,122.393 134.606,122.393 139.305,127.092 159.904,127.092 170.674,116.322 170.674,104.845 170.572,104.743 v1(170.572,93.183) 170.572,86.842 170.674,86.741 170.674,80.483 170.115,79.924 170.115,77.112 168.99,75.987 168.99,71.574 166.145,68.729 166.145,54.897 163.364,52.117 163.364,50.114 162.5,49.25 P8.48@162.5,49 162.5,47.638 163.437,46.701 163.437,45.187 162.5,44.25 P9.48@162.5,44
CAS0H#: CM6.1 RM18.2 UM3.21 UM4.21 | length 66
  Top Layer w0.203: UM3.21@90.392,117.54 92.823,117.54 93.484,116.879 98.972,116.879 99.633,117.54 UM4.21@105.4,117.54 ; v2(111.684,87.325) 120.077,87.325 CM6.1@121,88.248 123.098,88.248 RM18.2@123.1,88.25
  Bottom Layer w0.203: v2(99.466,117.297) 100.228,116.535 100.228,92.634 102.946,89.916 107.163,89.916 109.753,87.325 v2(111.684,87.325)
CAS0J0: RM17.1 U1.93 | length 15.5
  Top Layer w0.203: RM17.1@133.8,86.375 135.114,86.375 139.154,82.336 U1.93@147.647,82.336
CAS0J1: RM18.1 U1.92 | length 25.1
  Top Layer w0.203: RM18.1@124.8,88.25 126.153,88.25 126.976,87.427 134.926,87.427 139.517,82.836 U1.92@147.647,82.836
CAS0L#: CM5.1 RM17.2 UM1.21 UM2.21 | length 101
  Top Layer w0.203: UM1.21@60.375,117.54 64.426,117.54 65.086,116.879 73.175,116.879 73.771,117.475 79.451,117.475 80.01,116.916 v2(86.501,116.916) ; v2(86.512,118.135) 87.808,119.431 92.583,119.431 93.814,118.2 115.556,118.2 v2(116.662,117.094) ; v2(126.06,87.046) 126.06,86.665 127.254,85.471 129.094,85.471 CM5.1@130,86.377 132.098,86.377 RM17.2@132.1,86.375
  Bottom Layer w0.203: v2(86.501,116.916) 86.507,116.922 v2@86.507,118.13 ; v2(116.662,117.094) 116.648,117.08 116.648,111.673 126.06,102.26 v2(126.06,87.046)
CAS1H#: CM8.1 RM20.2 UM7.21 UM8.21 | length 33.6
  Top Layer w0.203: UM7.21@90.392,89.849 94.758,89.849 95.377,89.23 103.378,89.23 103.997,89.849 UM8.21@105.4,89.849 105.405,89.845 109.114,89.845 v2(109.118,89.84) ; v2(113.69,89.84) 116.876,89.84 117.206,89.51 120.386,89.51 121,90.124 123.099,90.124 RM20.2@123.1,90.125
  Bottom Layer w0.203: v2(109.118,89.84) v2(113.69,89.84)
CAS1J0: RM19.1 U1.91 | length 15.9
  Top Layer w0.203: RM19.1@133.8,88.25 134.916,88.25 139.83,83.336 U1.91@147.647,83.336
CAS1J1: RM20.1 U1.90 | length 25.5
  Top Layer w0.203: RM20.1@124.8,90.125 126.107,90.125 126.773,89.459 134.494,89.459 140.117,83.836 U1.90@147.647,83.836
CAS1L#: CM7.1 RM19.2 UM5.21 UM6.21 | length 77.5
  Top Layer w0.203: UM5.21@60.375,89.849 64.43,89.849 65.075,89.205 73.279,89.205 73.914,89.84 79.527,89.84 80.162,89.205 87.046,89.205 87.097,89.256 v2(88.671,89.256) ; v2(88.748,85.928) 102.908,85.928 103.289,86.309 109.474,86.309 112.217,89.052 129.2,89.052 CM7.1@130,88.252 130.013,88.265 v1(130.785,88.265) 132.085,88.265 RM19.2@132.1,88.25
  Bottom Layer w0.203: v2(88.671,89.256) 88.671,86.995 88.748,86.919 v2(88.748,85.928)
CAS2H#: CM10.1 P6.54 RM22.2 | length 37
  Top Layer w0.203: P6.54@99.32,75.62 99.32,77.399 v2(99.339,77.419) ; CM10.1@121,92 RM22.2@123.1,92
  Bottom Layer w0.203: v2(99.339,77.419) 100.228,77.419 104.089,81.28 118.897,81.28 121.768,84.15 v2(121.768,91.999)
CAS2J0: RM21.1 U1.89 | length 16.3
  Top Layer w0.203: RM21.1@133.833,90.322 133.941,90.214 134.501,90.214 140.379,84.336 U1.89@147.647,84.336
CAS2J1: RM22.1 U1.88 | length 25.8
  Top Layer w0.203: RM22.1@124.8,92 124.921,91.879 125.468,91.879 126.136,91.211 134.393,91.211 140.768,84.836 U1.88@147.647,84.836
CAS2L#: CM9.1 P6.53 RM21.2 | length 47.4
  Top Layer w0.203: CM9.1@130,90.127 130.043,90.17 132.055,90.17 RM21.2@132.1,90.125
  Bottom Layer w0.203: P6.53@99.3,73.6 99.3,73.566 99.668,73.198 99.702,73.198 100.764,72.136 106.02,72.136 106.782,72.898 106.782,76.556 108.737,78.511 123.647,78.511 132.156,87.02 132.156,88.951 131.319,89.788 131.319,90.169 v1(131.318,90.17)
CAS3H#: CM12.1 P6.52 RM24.2 | length 38.6
  Top Layer w0.203: v2(99.517,86.69) 108.788,86.69 114.96,92.862 119.987,92.862 CM12.1@121,93.875 RM24.2@123.1,93.875
  Bottom Layer w0.203: P6.52@97.3,75.6 97.333,75.633 97.333,76.454 99.517,78.638 v2(99.517,86.69)
CAS3J0: RM23.1 U1.87 | length 16.6
  Top Layer w0.203: RM23.1@133.8,92 134.493,92 141.157,85.336 U1.87@147.647,85.336
CAS3J1: RM24.1 U1.86 | length 26.2
  Top Layer w0.203: RM24.1@124.8,93.875 126.344,93.875 127.097,93.122 128.876,93.122 128.881,93.127 129.419,93.127 129.424,93.122 134.336,93.122 141.623,85.836 U1.86@147.647,85.836
CAS3L#: CM11.1 P6.51 RM23.2 | length 46.5
  Top Layer w0.203: CM11.1@130,92.002 130.002,92 v2(131.051,92) RM23.2@132.1,92
  Bottom Layer w0.203: P6.51@97.3,73.6 97.3,73.85 98.298,74.848 98.298,76.327 98.806,76.835 101.727,76.835 104.826,79.934 122.479,79.934 128.6,86.055 128.6,89.549 v2(131.051,92)
CHGLED: P6.59 UP1.6 | length 208.7
  Top Layer w0.203: P6.59@105.3,73.6 105.3,73.85 106.401,74.951 106.401,76.175 107.239,77.013 108.56,77.013 109.55,78.003 121.615,78.003 122.022,77.597 130.226,77.597 130.572,77.251 135.372,77.251 v1(135.738,76.886) ; v1(120.915,23.216) 134.823,23.216 v1(139.192,18.847)
  Top Layer w0.508: UP1.6@217.13,19.066 217.869,19.066 v1(218.301,18.634)
  Bottom Layer w0.203: v1(120.915,23.216) 120.915,43.678 128.702,51.465 128.702,57.125 132.639,61.062 132.639,70.383 135.738,73.482 v1(135.738,76.886) ; v1(139.192,18.847) 139.192,18.797 143.918,14.072 151.359,14.072 153.019,12.411 203.287,12.411 204.634,13.757 204.634,21.783 205.827,22.977 216.064,22.977 218.301,20.74 v1(218.301,18.634)
CLK2: P6.20 U1.39 X1.3 | length 154.4
  Top Layer w0.254: P6.20@65.3,75.6 65.3,75.648 65.645,75.993 65.693,75.993 66.627,76.927 84.691,76.927 84.808,76.81 v1(96.317,76.81) ; v1(97.688,105.359) 98.806,105.359 100.191,106.745 106.374,106.745 106.376,106.746 107.809,106.746 112.779,111.716 139.847,111.716 141.692,109.871 153.097,109.871 156.805,106.163 U1.39@156.805,104.994 156.805,103.293 158.812,101.285 162.419,101.285 164.07,102.936 v1(165.975,102.936) ; v1(161.239,113.208) X1.3@161.239,116.072
  Bottom Layer w0.254: v1(96.317,76.81) 96.317,76.87 95.199,77.987 95.199,88.951 96.418,90.17 96.418,104.089 v1(97.688,105.359) ; v1(161.239,113.208) 165.975,108.472 v1(165.975,102.936)
COM2RxD: U2.6 U12.88 | length 140.9
  Top Layer w0.203: U12.88@28.301,83.654 28.301,81.17 33.331,76.139 40.118,76.139 41.921,77.943 49.313,77.943 50.379,76.876 v1(52.183,76.876) ; v1(65.253,20.041) 78.762,20.041 79.423,20.701 103.607,20.701 109.205,15.103 U2.6@110.431,15.103
  Bottom Layer w0.203: v1(52.183,76.876) 52.124,76.818 52.124,76.351 52.114,76.341 52.114,71.788 60.565,63.338 62.549,63.338 65.253,60.634 v1(65.253,20.041)
COM2TxD: U2.5 U12.89 | length 139.3
  Top Layer w0.203: U12.89@28.951,83.654 28.951,81.439 33.641,76.749 39.889,76.749 41.591,78.451 49.617,78.451 v1(50.633,77.435) ; v1(64.686,20.599) 78.638,20.599 79.223,21.184 103.81,21.184 109.391,15.603 U2.5@110.431,15.603
  Bottom Layer w0.203: v1(50.633,77.435) 50.633,76.322 50.495,76.183 50.495,72.595 60.311,62.779 62.317,62.779 64.73,60.366 64.73,38.185 64.643,38.097 64.643,20.643 v1(64.686,20.599)
COM_CTS#: DB2.8 U13.4 | length 16.9
  Top Layer w0.254: U13.4@144.2,124.4 143.089,124.4 142.251,125.238 142.251,128.006 143.775,129.53 143.775,135.728 144.45,136.402 145.197,136.402 146.215,137.42 DB2.8@146.215,137.72
COM_DCD#: DB2.1 U13.18 | length 16.7
  Top Layer w0.254: U13.18@152,119.85 152.073,119.923 152.989,119.923 153.935,120.869 153.935,133.577 153.14,134.372 DB2.1@153.14,134.88
COM_DSR#: DB2.6 U13.23 | length 16.4
  Top Layer w0.254: DB2.6@151.755,137.72 151.755,133.057 153.275,131.537 153.275,123.282 153.093,123.1 U13.23@152,123.1
COM_DTR#: DB2.4 U13.2 | length 11.1
  Top Layer w0.254: U13.2@144.2,125.7 144.192,125.708 143.177,125.708 142.937,125.949 142.937,127.6 144.83,129.493 DB2.4@144.83,134.88
COM_RI#: DB2.9 U13.9 | length 19.2
  Top Layer w0.254: DB2.9@143.445,137.72 143.445,137.164 143.089,136.808 143.089,129.987 141.515,128.413 141.515,124.73 142.708,123.536 142.708,121.453 143.011,121.15 U13.9@144.2,121.15
COM_RTS#: DB2.7 U13.1 | length 13.8
  Top Layer w0.254: U13.1@144.2,126.35 144.2,127.618 145.909,129.327 145.909,135.042 147.269,136.402 147.967,136.402 148.985,137.42 DB2.7@148.985,137.72
COM_RxD: DB2.2 U13.27 | length 10.6
  Top Layer w0.254: DB2.2@150.37,134.88 150.37,126.09 150.76,125.7 U13.27@152,125.7
COM_TxD: DB2.3 U13.3 | length 11.9
  Top Layer w0.254: U13.3@144.2,125.05 145.264,125.05 145.68,125.466 145.68,127.549 146.823,128.692 146.823,133.803 147.6,134.58 DB2.3@147.6,134.88
COVOXEN#: P11.5 U2.26 | length 123.5
  Top Layer w0.203: U2.26@118.581,12.603 120.273,12.603 127.381,19.71 v2(134.62,19.71)
  Bottom Layer w0.203: v2(134.62,19.71) 140.614,25.705 178.105,25.705 190.602,38.202 208.204,38.202 209.296,39.294 221.818,39.294 225.349,42.824 225.882,42.824 226.339,43.282 226.339,44.729 225.5,45.569 P11.5@225.5,46
CTP_INT: P4.8
CTP_RST: P4.9 R15.1 | length 7.5
  Top Layer w0.203: R15.1@120.999,122.587 121.839,122.587 123.811,120.615 126.065,120.615 127.05,121.6 P4.9@127.3,121.6
CTP_SCL: P4.4 R8.1 | length 4.3
  Top Layer w0.203: R8.1@120.999,115.649 121.048,115.6 P4.4@125.3,115.6
CTP_SDA: P4.5 R13.1 | length 6.8
  Top Layer w0.203: R13.1@120.999,117.037 121.282,116.754 126.204,116.754 127.05,117.6 P4.5@127.3,117.6
CTS1#: U12.82 U13.5 | length 149.6
  Top Layer w0.203: v1(24.395,85.309) 24.398,85.306 24.398,83.657 U12.82@24.401,83.654 ; U13.5@144.2,123.75 146.253,123.75 148.195,121.809 v1(148.195,117.592)
  Layer 2 w0.203: v1(24.395,85.309) 26.251,83.453 47.849,83.453 61.008,96.612 62.1,96.612 68.781,103.292 132.273,103.292 146.878,117.897 147.314,117.897 147.619,117.592 v1(148.195,117.592)
DACK0#: P7.31 P8.56 P9.56 R21.2 U1.16 | length 192
  Top Layer w0.203: v1(78.294,121.021) 79.238,121.021 79.519,120.74 113.223,120.74 118.747,126.264 v1(121.271,126.264) ; U1.16@168.305,104.994 168.308,104.997 168.308,107.301 v1(168.363,107.356)
  Bottom Layer w0.203: P7.31@77.3,129.2 77.3,125.9 R21.2@77.5,125.7 77.5,125.662 76.592,124.754 76.592,122.723 v1(78.294,121.021) ; v1(121.271,126.264) 121.329,126.205 121.329,125.713 124.256,122.786 128.803,122.786 130.68,120.909 135.306,120.909 139.967,125.57 159.242,125.57 168.997,115.814 168.997,108.042 v1@168.312,107.356 ; P9.56@154.5,44 154.5,44.25 155.437,45.187 155.437,46.701 154.5,47.638 P8.56@154.5,49 154.5,49.25 155.485,50.235 155.485,51.73 158.609,54.854 158.609,68.973 161.776,72.14 161.776,76.204 165.947,80.375 165.947,81.598 167.776,83.427 167.776,106.82 v1@168.312,107.356 ; v1(168.363,107.356) v1@168.312,107.356
DACK1#: P5.33 P8.14 P9.14 R25.2 U1.18 U12.28 | length 288.1
  Top Layer w0.203: U12.28@39.026,104.129 40.447,104.129 40.931,104.613 40.931,106.264 44.263,109.597 49.764,109.597 50.051,109.31 53.197,109.31 v1(53.199,109.312) ; P5.33@62.87,133.9 62.87,134.2 61.784,135.286 61.784,139.106 62.492,139.814 106.897,139.814 116.38,130.332 v1(116.459,130.332) ; U1.18@167.305,104.994 167.305,108.025 168.134,108.855 181.85,108.855 v1(184.314,111.318)
  Bottom Layer w0.203: v1(53.199,109.312) 53.205,109.312 61.017,117.123 61.017,126.782 62.114,127.879 62.114,132.771 62.87,133.527 P5.33@62.87,133.9 62.87,134.2 61.825,135.245 R25.2@61.825,138.7 ; v1(116.459,130.332) 116.459,130.253 116.954,129.757 122.539,129.757 123.577,130.795 128.352,130.795 128.611,131.054 140.009,131.054 164.581,131.054 184.304,111.331 184.304,111.309 186.699,108.914 186.699,97.487 189.343,94.843 189.343,60.187 197.419,52.111 197.419,50.169 196.5,49.25 196.5,47.638 197.437,46.701 197.437,45.187 196.5,44.25 P9.14@196.5,44
DACK2#: P5.51 P8.46 P9.46 U1.20 U12.36 | length 259.9
  Top Layer w0.203: U12.36@32.851,108.354 32.851,110.046 47.662,124.857 81.748,124.857 84.263,127.371 84.263,132.133 85.73,133.6 P5.51@85.73,133.9 ; v1(86.498,123.002) 96.125,123.002 96.709,122.418 113.374,122.418 115.557,124.601 115.557,124.655 117.74,126.838 121.753,126.838 122.084,126.508 122.084,125.441 122.729,124.795 128.67,124.795 128.703,124.763 128.883,124.763 v1(128.91,124.789) ; U1.20@166.305,104.994 166.305,108.524 167.727,109.947 v1(171.258,109.947)
  Bottom Layer w0.203: P5.51@85.73,133.9 85.73,133.6 86.486,132.844 v1@86.486,123.002 ; v1(128.91,124.789) 128.856,124.789 128.383,125.263 128.383,126.025 130.516,128.159 159.65,128.159 171.258,116.551 v1(171.258,109.947) 171.258,76.825 170.001,75.568 170.001,71.155 167.156,68.311 167.156,54.359 165.549,52.752 165.549,50.299 164.5,49.25 P8.46@164.5,49 164.5,47.638 165.437,46.701 165.437,45.187 164.5,44.25 P9.46@164.5,44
